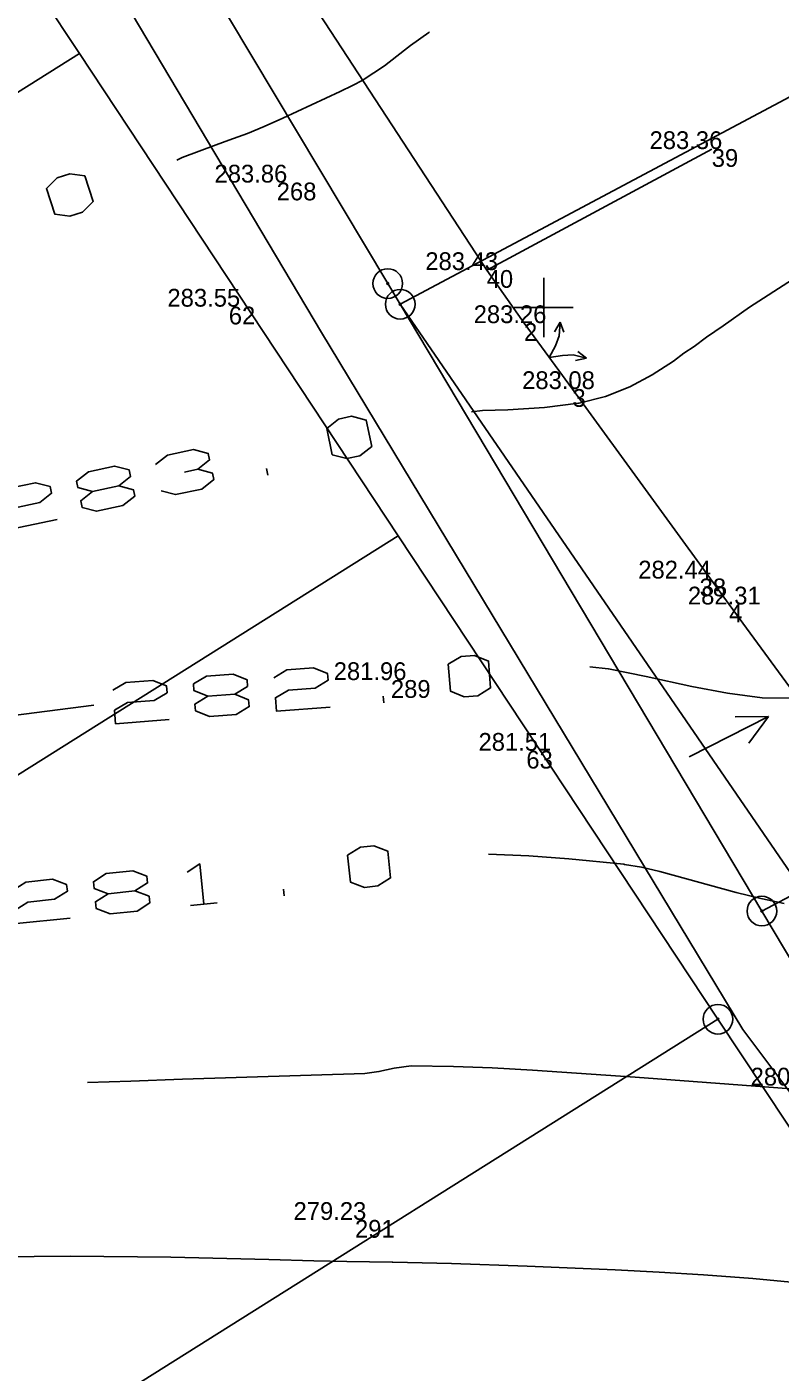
# Model space of a CAD drawing. Extents: x -771260 to -770828, y -1053564 to -1052811.
# Drawn here: x -771067.43 to -771042.02, y -1053135.91 to -1053090.53 of the extents above; entities that cross this region are included whole.
import ezdxf

# ---------------------------------------------------------------- set-up
doc = ezdxf.new("R2010")
doc.units = 0
for name, color, linetype in [('14_8_2023_krizky', 7, 'Continuous'), ('22_4_2022_plot', 7, 'Continuous'), ('22_4_2022_plot_vstup', 7, 'Continuous'), ('22_4_2022_zamereny_bod', 7, 'Continuous'), ('22_4_2022_zamereny_bod_cislo', 7, 'Continuous'), ('22_4_2022_zamereny_bod_vyska', 7, 'Continuous'), ('25_3_2019_krizky_JTSK', 7, 'Continuous'), ('25_3_2019_oploceni', 7, 'Continuous'), ('25_3_2019_vrstevnice_interval_po_1m', 7, 'Continuous'), ('25_3_2019_zamereny_bod', 7, 'Continuous'), ('25_3_2019_zamereny_bod_cislo', 7, 'Continuous'), ('25_3_2019_zamereny_bod_vyska', 7, 'Continuous'), ('Default', 7, 'Continuous'), ('DKM_Hranice parcel', 7, 'Continuous'), ('DKM_Pop  PČ popisy', 7, 'Continuous'), ('DKM_Značky bodu BP', 7, 'Continuous')]:
    doc.layers.add(name, color=color, linetype=linetype)

# ---------------------------------------------------------------- blocks, each defined once
blk = doc.blocks.new('POINT_DISPLAY')
at = {"layer": 'Default'}
blk.add_line((0, 0), (0, 0), dxfattribs=at)
blk = doc.blocks.new('KRIZEK')
at = {"layer": '25_3_2019_krizky_JTSK'}
for p, q in [((0, 10), (0, -10)), ((-10, 0), (10, 0))]:
    blk.add_line(p, q, dxfattribs=at)

msp = doc.modelspace()

# ---------------------------------------------------------------- linework, layer by layer
at = {"layer": '22_4_2022_plot'}
for p, q in [((-771051.923, -1053098.736), (-771050.662, -1053100.526)), ((-771049.029, -1053102.751), (-771043.746, -1053110.018)), ((-771043.746, -1053110.018), (-771038.034, -1053117.822))]:
    msp.add_line(p, q, dxfattribs=at)
at = {"layer": '22_4_2022_plot_vstup'}
for p, q in [((-771050.662, -1053100.526), (-771049.029, -1053102.751)), ((-771049.442, -1053100.491), (-771049.637, -1053100.818)), ((-771049.442, -1053100.491), (-771049.479, -1053100.951)), ((-771049.442, -1053100.491), (-771049.317, -1053100.833)), ((-771049.479, -1053100.951), (-771049.604, -1053101.289)), ((-771049.604, -1053101.289), (-771049.81, -1053101.686)), ((-771049.81, -1053101.686), (-771049.369, -1053101.613)), ((-771049.369, -1053101.613), (-771049.008, -1053101.598)), ((-771049.008, -1053101.598), (-771048.56, -1053101.705)), ((-771048.56, -1053101.705), (-771048.847, -1053101.48)), ((-771048.56, -1053101.705), (-771048.931, -1053101.789))]:
    msp.add_line(p, q, dxfattribs=at)
at = {"layer": '22_4_2022_zamereny_bod'}
for p, q in [((-771050.662, -1053100.526), (-771050.662, -1053100.526)), ((-771049.029, -1053102.751), (-771049.029, -1053102.751)), ((-771043.746, -1053110.018), (-771043.746, -1053110.018))]:
    msp.add_line(p, q, dxfattribs=at)
at = {"layer": '25_3_2019_oploceni'}
for p, q in [((-771058.365, -1053088.862), (-771051.922, -1053098.735)), ((-771051.922, -1053098.735), (-771044.331, -1053094.654))]:
    msp.add_line(p, q, dxfattribs=at)
at = {"layer": '25_3_2019_vrstevnice_interval_po_1m'}
for points in [[(-771062.377, -1053095.026), (-771062.191, -1053094.943), (-771061.053, -1053094.511), (-771060.623, -1053094.355), (-771059.993, -1053094.128), (-771059.425, -1053093.891), (-771058.805, -1053093.606), (-771056.864, -1053092.716), (-771056.451, -1053092.512), (-771056.106, -1053092.326), (-771056.092, -1053092.319), (-771055.375, -1053091.846), (-771054.691, -1053091.322), (-771054.492, -1053091.16), (-771053.875, -1053090.716), (-771053.854, -1053090.701)], [(-771054.492, -1053091.16), (-771054.492, -1053091.16)], [(-771054.691, -1053091.322), (-771054.691, -1053091.322)], [(-771055.375, -1053091.846), (-771055.375, -1053091.846)], [(-771056.451, -1053092.512), (-771056.451, -1053092.512)], [(-771056.092, -1053092.319), (-771056.092, -1053092.319)], [(-771056.864, -1053092.716), (-771056.864, -1053092.716)], [(-771059.425, -1053093.891), (-771059.425, -1053093.891)], [(-771059.993, -1053094.128), (-771059.993, -1053094.128)], [(-771061.053, -1053094.511), (-771061.053, -1053094.511)], [(-771062.377, -1053095.026), (-771062.377, -1053095.026)], [(-771062.191, -1053094.943), (-771062.191, -1053094.943)], [(-771065.99, -1053096.923), (-771066.492, -1053096.848), (-771066.774, -1053095.985), (-771066.413, -1053095.629), (-771065.982, -1053095.488), (-771065.48, -1053095.562), (-771065.198, -1053096.425), (-771065.559, -1053096.782), (-771065.99, -1053096.923)], [(-771052.439, -1053103.514), (-771052.069, -1053103.476), (-771051.204, -1053103.451), (-771049.976, -1053103.378), (-771048.823, -1053103.227), (-771048.804, -1053103.224), (-771047.917, -1053103.002), (-771047.099, -1053102.678), (-771046.339, -1053102.272), (-771045.619, -1053101.807), (-771045.268, -1053101.545), (-771044.921, -1053101.31), (-771044.51, -1053101), (-771044.505, -1053100.997), (-771043.945, -1053100.62), (-771043.057, -1053099.993), (-771041.611, -1053099.055), (-771041.353, -1053098.898), (-771041.339, -1053098.889)], [(-771043.057, -1053099.993), (-771043.057, -1053099.993)], [(-771043.945, -1053100.62), (-771043.945, -1053100.62)], [(-771044.505, -1053100.997), (-771044.505, -1053100.997)], [(-771045.268, -1053101.545), (-771045.268, -1053101.545)], [(-771044.921, -1053101.31), (-771044.921, -1053101.31)], [(-771045.619, -1053101.807), (-771045.619, -1053101.807)], [(-771046.339, -1053102.272), (-771046.339, -1053102.272)], [(-771047.099, -1053102.678), (-771047.099, -1053102.678)], [(-771049.976, -1053103.378), (-771049.976, -1053103.378)], [(-771048.804, -1053103.224), (-771048.804, -1053103.224)], [(-771047.917, -1053103.002), (-771047.917, -1053103.002)], [(-771056.642, -1053105.094), (-771057.133, -1053104.966), (-771057.32, -1053104.077), (-771056.923, -1053103.762), (-771056.479, -1053103.668), (-771055.988, -1053103.797), (-771055.801, -1053104.685), (-771056.198, -1053105.001), (-771056.642, -1053105.094)], [(-771052.439, -1053103.514), (-771052.439, -1053103.514)], [(-771052.069, -1053103.476), (-771052.069, -1053103.476)], [(-771051.204, -1053103.451), (-771051.204, -1053103.451)], [(-771063.094, -1053105.293), (-771062.696, -1053104.977), (-771061.808, -1053104.79), (-771061.317, -1053104.919), (-771061.271, -1053105.141), (-771061.668, -1053105.456)], [(-771064.333, -1053106.017), (-771063.935, -1053105.702), (-771063.982, -1053105.48), (-771064.473, -1053105.351), (-771065.361, -1053105.538), (-771065.759, -1053105.854), (-771065.712, -1053106.076), (-771065.221, -1053106.204)], [(-771061.668, -1053105.456), (-771061.177, -1053105.585), (-771061.13, -1053105.807), (-771061.528, -1053106.123), (-771062.416, -1053106.309), (-771062.907, -1053106.181)], [(-771061.668, -1053105.456), (-771062.112, -1053105.55)], [(-771059.307, -1053105.655), (-771059.354, -1053105.433)], [(-771068.423, -1053106.414), (-771068.026, -1053106.099), (-771067.138, -1053105.912), (-771066.647, -1053106.04), (-771066.6, -1053106.263), (-771066.998, -1053106.578), (-771067.886, -1053106.765), (-771068.283, -1053107.081), (-771068.19, -1053107.525), (-771066.413, -1053107.151)], [(-771064.333, -1053106.017), (-771063.842, -1053106.146), (-771063.795, -1053106.368), (-771064.193, -1053106.683), (-771065.081, -1053106.87), (-771065.572, -1053106.742), (-771065.618, -1053106.52), (-771065.221, -1053106.204)], [(-771065.221, -1053106.204), (-771064.333, -1053106.017)], [(-771048.448, -1053112.12), (-771047.823, -1053112.191), (-771047.809, -1053112.193), (-771046.538, -1053112.448), (-771045.005, -1053112.783), (-771043.794, -1053113.013), (-771042.626, -1053113.163), (-771041.624, -1053113.175), (-771041.602, -1053113.175), (-771040.615, -1053113.074), (-771039.741, -1053112.937), (-771038.854, -1053112.762), (-771037.99, -1053112.557), (-771037.143, -1053112.329), (-771036.363, -1053112.1), (-771036.327, -1053112.09), (-771035.455, -1053111.794), (-771034.864, -1053111.613), (-771034.592, -1053111.517), (-771034.173, -1053111.387), (-771033.743, -1053111.221), (-771033.43, -1053111.11), (-771032.924, -1053110.908), (-771032.909, -1053110.902)], [(-771052.678, -1053113.13), (-771053.148, -1053112.938), (-771053.218, -1053112.033), (-771052.783, -1053111.772), (-771052.33, -1053111.737), (-771051.86, -1053111.928), (-771051.79, -1053112.833), (-771052.225, -1053113.095), (-771052.678, -1053113.13)], [(-771060.423, -1053113.046), (-771059.988, -1053112.784), (-771060.005, -1053112.558), (-771060.475, -1053112.367), (-771061.38, -1053112.437), (-771061.815, -1053112.698), (-771061.798, -1053112.924), (-771061.328, -1053113.116)], [(-771059.1, -1053112.488), (-771058.665, -1053112.227), (-771057.76, -1053112.157), (-771057.29, -1053112.348), (-771057.273, -1053112.574), (-771057.708, -1053112.836), (-771058.613, -1053112.906), (-771059.048, -1053113.167), (-771059.013, -1053113.619), (-771057.203, -1053113.479)], [(-771048.448, -1053112.12), (-771048.448, -1053112.12)], [(-771047.823, -1053112.191), (-771047.823, -1053112.191)], [(-771046.538, -1053112.448), (-771046.538, -1053112.448)], [(-771064.531, -1053112.908), (-771064.096, -1053112.647), (-771063.19, -1053112.577), (-771062.72, -1053112.768), (-771062.703, -1053112.994), (-771063.138, -1053113.256), (-771064.043, -1053113.326), (-771064.478, -1053113.587), (-771064.443, -1053114.039), (-771062.633, -1053113.899)], [(-771045.005, -1053112.783), (-771045.005, -1053112.783)], [(-771069.127, -1053113.923), (-771065.174, -1053113.413)], [(-771060.423, -1053113.046), (-771059.953, -1053113.237), (-771059.935, -1053113.463), (-771060.37, -1053113.724), (-771061.275, -1053113.794), (-771061.745, -1053113.603), (-771061.763, -1053113.377), (-771061.328, -1053113.116)], [(-771061.328, -1053113.116), (-771060.423, -1053113.046)], [(-771055.393, -1053113.339), (-771055.41, -1053113.113)], [(-771043.794, -1053113.013), (-771043.794, -1053113.013)], [(-771042.626, -1053113.163), (-771042.626, -1053113.163)], [(-771056.044, -1053119.562), (-771056.519, -1053119.383), (-771056.613, -1053118.48), (-771056.185, -1053118.208), (-771055.733, -1053118.161), (-771055.258, -1053118.34), (-771055.165, -1053119.243), (-771055.593, -1053119.515), (-771056.044, -1053119.562)], [(-771062.03, -1053119.044), (-771061.602, -1053118.771), (-771061.461, -1053120.125)], [(-771051.863, -1053118.443), (-771051.863, -1053118.443)], [(-771051.863, -1053118.443), (-771051.86, -1053118.443), (-771050.503, -1053118.503), (-771049.157, -1053118.6), (-771047.299, -1053118.784), (-771047.273, -1053118.787), (-771046.697, -1053118.883), (-771046.08, -1053119.028), (-771043.502, -1053119.732), (-771042.679, -1053119.935), (-771042.614, -1053119.951), (-771041.883, -1053120.109)], [(-771050.503, -1053118.503), (-771050.503, -1053118.503)], [(-771049.157, -1053118.6), (-771049.157, -1053118.6)], [(-771047.273, -1053118.787), (-771047.273, -1053118.787)], [(-771067.899, -1053119.654), (-771067.471, -1053119.381), (-771066.568, -1053119.287), (-771066.093, -1053119.466), (-771066.069, -1053119.692), (-771066.497, -1053119.964), (-771067.4, -1053120.058), (-771067.828, -1053120.331), (-771067.781, -1053120.782), (-771065.976, -1053120.595)], [(-771063.789, -1053119.683), (-771063.361, -1053119.41), (-771063.384, -1053119.184), (-771063.859, -1053119.006), (-771064.762, -1053119.099), (-771065.19, -1053119.372), (-771065.167, -1053119.598), (-771064.692, -1053119.777)], [(-771046.697, -1053118.883), (-771046.697, -1053118.883)], [(-771046.08, -1053119.028), (-771046.08, -1053119.028)], [(-771063.789, -1053119.683), (-771063.314, -1053119.862), (-771063.29, -1053120.087), (-771063.718, -1053120.36), (-771064.621, -1053120.454), (-771065.096, -1053120.275), (-771065.12, -1053120.049), (-771064.692, -1053119.777)], [(-771064.692, -1053119.777), (-771063.789, -1053119.683)], [(-771058.753, -1053119.844), (-771058.776, -1053119.618)], [(-771043.502, -1053119.732), (-771043.502, -1053119.732)], [(-771061.913, -1053120.172), (-771061.01, -1053120.078)], [(-771042.614, -1053119.951), (-771042.614, -1053119.951)], [(-771065.394, -1053126.148), (-771063.928, -1053126.095), (-771062.179, -1053126.031), (-771056.037, -1053125.843), (-771056.034, -1053125.842), (-771055.557, -1053125.775), (-771055.043, -1053125.66), (-771054.471, -1053125.585), (-771054.468, -1053125.585), (-771053.042, -1053125.602), (-771051.733, -1053125.653), (-771050.38, -1053125.731), (-771046.919, -1053125.97), (-771041.344, -1053126.378)], [(-771055.043, -1053125.66), (-771055.043, -1053125.66)], [(-771054.471, -1053125.585), (-771054.471, -1053125.585)], [(-771053.042, -1053125.602), (-771053.042, -1053125.602)], [(-771051.733, -1053125.653), (-771051.733, -1053125.653)], [(-771062.179, -1053126.031), (-771062.179, -1053126.031)], [(-771056.034, -1053125.842), (-771056.034, -1053125.842)], [(-771055.557, -1053125.775), (-771055.557, -1053125.775)], [(-771050.38, -1053125.731), (-771050.38, -1053125.731)], [(-771046.919, -1053125.97), (-771046.919, -1053125.97)], [(-771065.394, -1053126.148), (-771065.394, -1053126.148)], [(-771068.42, -1053132.026), (-771065.967, -1053132.003), (-771062.58, -1053132.034), (-771059.268, -1053132.118), (-771057.755, -1053132.156), (-771056.638, -1053132.179), (-771055.115, -1053132.21), (-771055.09, -1053132.21), (-771053.107, -1053132.255), (-771050.561, -1053132.336), (-771047.585, -1053132.464), (-771046.099, -1053132.541), (-771044.614, -1053132.631), (-771042.945, -1053132.76), (-771041.655, -1053132.882)], [(-771065.967, -1053132.003), (-771065.967, -1053132.003)], [(-771062.58, -1053132.034), (-771062.58, -1053132.034)], [(-771057.755, -1053132.156), (-771057.755, -1053132.156)], [(-771055.09, -1053132.21), (-771055.09, -1053132.21)], [(-771053.107, -1053132.255), (-771053.107, -1053132.255)], [(-771050.561, -1053132.336), (-771050.561, -1053132.336)], [(-771047.585, -1053132.464), (-771047.585, -1053132.464)], [(-771046.099, -1053132.541), (-771046.099, -1053132.541)], [(-771044.614, -1053132.631), (-771044.614, -1053132.631)], [(-771042.945, -1053132.76), (-771042.945, -1053132.76)]]:
    msp.add_lwpolyline(points, dxfattribs=at)
at = {"layer": 'DKM_Hranice parcel'}
for p, q in [((-771065.66, -1053091.43), (-771073.41, -1053079.72)), ((-771054.84, -1053099.89), (-771019.12, -1053080.86)), ((-771080.25, -1053100.58), (-771065.66, -1053091.43)), ((-771065.66, -1053091.43), (-771054.91, -1053107.7)), ((-771054.84, -1053099.89), (-771041.28, -1053119.65)), ((-771054.84, -1053099.89), (-771042.64, -1053120.36)), ((-771054.91, -1053107.7), (-771106.48, -1053140.11)), ((-771054.91, -1053107.7), (-771044.12, -1053124.01)), ((-771041.28, -1053119.65), (-771042.64, -1053120.36)), ((-771044.12, -1053124.01), (-771095.9, -1053156.55)), ((-771044.12, -1053124.01), (-771032.21, -1053142.02))]:
    msp.add_line(p, q, dxfattribs=at)
for points in [[(-771070.11, -1053079.64), (-771069.54, -1053080.6), (-771057.49, -1053100.84), (-771043.28, -1053124.36), (-771026.92, -1053146.17), (-771010.22, -1053166.92)], [(-771066.73, -1053080.01), (-771055.26, -1053099.19), (-771054.84, -1053099.89)], [(-771029.17, -1053140.37), (-771039.2, -1053126.13), (-771042.64, -1053120.36)]]:
    msp.add_lwpolyline(points, dxfattribs=at)
at = {"layer": 'DKM_Pop  PČ popisy'}
for p, q in [((-771045.09, -1053115.16), (-771042.416, -1053113.798)), ((-771042.416, -1053113.798), (-771043.536, -1053113.806)), ((-771042.416, -1053113.798), (-771043.081, -1053114.698))]:
    msp.add_line(p, q, dxfattribs=at)
at = {"layer": 'DKM_Značky bodu BP'}
for centre, radius in [((-771055.26, -1053099.19), 0.5), ((-771055.26, -1053099.19), 0.0303), ((-771054.84, -1053099.89), 0.5), ((-771054.84, -1053099.89), 0.0303), ((-771042.64, -1053120.36), 0.5), ((-771042.64, -1053120.36), 0.0303), ((-771044.12, -1053124.01), 0.5), ((-771044.12, -1053124.01), 0.0303)]:
    msp.add_circle(centre, radius, dxfattribs=at)

# ---------------------------------------------------------------- block references
at = {"layer": '14_8_2023_krizky', "xscale": 0.1, "yscale": 0.10000000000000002}
msp.add_blockref('KRIZEK', (-771050, -1053100), dxfattribs=at)
at = {"layer": '25_3_2019_zamereny_bod', "xscale": 0.1, "yscale": 0.10000000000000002}
for p in [(-771044.331, -1053094.654), (-771059.006, -1053095.784), (-771051.923, -1053098.736), (-771060.623, -1053099.97), (-771044.739, -1053109.142), (-771055.154, -1053112.568), (-771050.585, -1053114.953), (-771056.366, -1053130.781)]:
    msp.add_blockref('POINT_DISPLAY', p, dxfattribs=at)

# ---------------------------------------------------------------- texts
at = {"layer": '22_4_2022_zamereny_bod_cislo'}
for s, p in [('2', (-771050.662, -1053101.126)), ('3', (-771049.029, -1053103.351)), ('4', (-771043.746, -1053110.618))]:
    msp.add_text(s, height=0.6, dxfattribs=at).set_placement(p)
at = {"layer": '22_4_2022_zamereny_bod_vyska'}
for s, p in [('283.26 ', (-771052.362, -1053100.526)), ('283.08 ', (-771050.727, -1053102.751)), ('282.31 ', (-771045.134, -1053110.018))]:
    msp.add_text(s, height=0.6, dxfattribs=at).set_placement(p)
at = {"layer": '25_3_2019_zamereny_bod_cislo'}
for s, p in [('39', (-771044.331, -1053095.254)), ('268', (-771059.006, -1053096.384)), ('40', (-771051.923, -1053099.336)), ('62', (-771060.623, -1053100.57)), ('38', (-771044.739, -1053109.742)), ('289', (-771055.154, -1053113.168)), ('63', (-771050.585, -1053115.553)), ('291', (-771056.366, -1053131.381))]:
    msp.add_text(s, height=0.6, dxfattribs=at).set_placement(p)
at = {"layer": '25_3_2019_zamereny_bod_vyska'}
for s, p in [('283.36 ', (-771046.429, -1053094.654)), ('283.86 ', (-771061.104, -1053095.784)), ('283.43 ', (-771053.993, -1053098.736)), ('283.55 ', (-771062.693, -1053099.97)), ('282.44 ', (-771046.809, -1053109.142)), ('281.96 ', (-771057.083, -1053112.568)), ('281.51 ', (-771052.199, -1053114.953)), ('280.03 ', (-771043.019, -1053126.247)), ('279.23 ', (-771058.438, -1053130.781))]:
    msp.add_text(s, height=0.6, dxfattribs=at).set_placement(p)

doc.saveas('drawing.dxf')
